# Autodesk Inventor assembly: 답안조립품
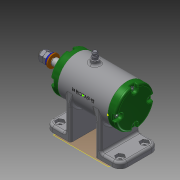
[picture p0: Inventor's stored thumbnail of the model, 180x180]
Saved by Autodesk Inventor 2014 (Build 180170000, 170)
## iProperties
Created: 2017-02
Part Number: 답안조립품
Document SubType Name: Assembly
Designer: owner
Author: owner
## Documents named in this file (16)
- C:\Users\owner\Desktop\470207V1001\답안조립품.iam
- C:\Users\owner\Desktop\470207V1001\본체1.ipt
- C:\Users\owner\Desktop\470207V1001\축.ipt
- C:\Users\owner\Desktop\470207V1001\베어링 15 x 32 x 9.ipt
- C:\Users\owner\Desktop\470207V1001\키 3 x 3 x 12.ipt
- C:\Users\owner\Desktop\470207V1001\V벨트풀리.ipt
- C:\Users\owner\Desktop\470207V1001\와셔 8x17.ipt
- C:\Users\owner\Desktop\470207V1001\스프링와셔 8.ipt
- C:\Users\owner\Desktop\470207V1001\너트 M 8.ipt
- C:\Users\owner\Desktop\470207V1001\앞커버.ipt
- C:\Users\owner\Desktop\470207V1001\오일 실 15 25 7.ipt
- C:\Users\owner\Desktop\470207V1001\뒤커버.ipt
- C:\Users\owner\Desktop\470207V1001\볼트 M4 x 12.ipt
- C:\Users\owner\Desktop\470207V1001\니플 M 6 x 0.75.ipt
- C:\Users\owner\Desktop\470207V1001\와셔 6x11.5.ipt
- C:\Users\owner\Desktop\470207V1001\볼트 M 6 x 8.ipt
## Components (8 placed, 3 different names)
1. KS B 2023 6002 - 15 x 32 x 9:1
2. KS B 2023 6002 - 15 x 32 x 9:2
3. V벨트풀리:1 — 각도:2
4. ISO 4762 M4 x 12:2
5. ISO 4762 M4 x 12:1
6. ISO 4762 M4 x 12:3
7. ISO 4762 M4 x 12:4
8. ISO 4762 M4 x 12:5
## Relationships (1: Angle 1)
- 각도:2 [Angle]: V벨트풀리:1
